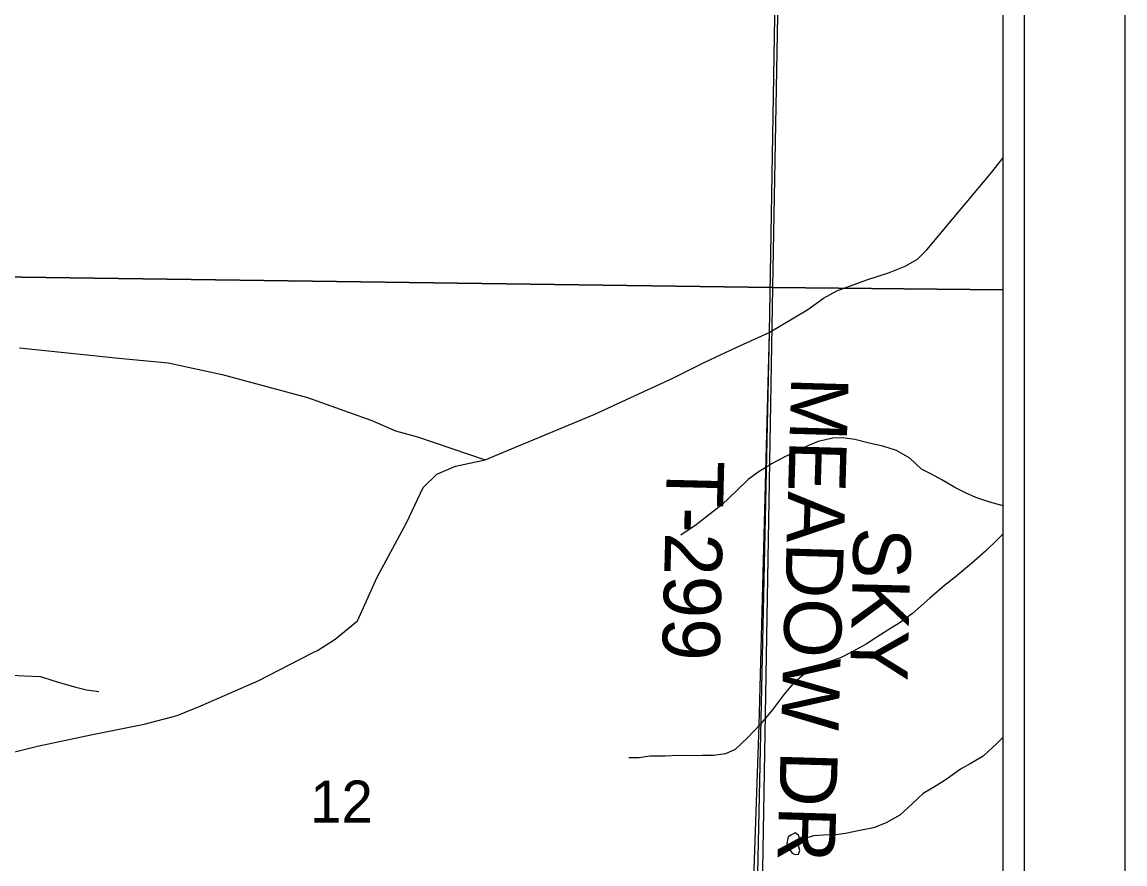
# Model space of a CAD drawing. Extents: x 0 to 34, y -2.3 to 22.
# Drawn here: x 7.907 to 9, y 18.764 to 19.599 of the extents above; entities that cross this region are included whole.
import ezdxf

# ---------------------------------------------------------------- set-up
doc = ezdxf.new("R2010")
doc.units = 0
for name, color, linetype in [('GM_X_County', 7, 'Continuous'), ('GM_X_Minor_River', 7, 'Continuous'), ('GM_X_Section', 7, 'Continuous'), ('GM_X_Section_Text', 7, 'Continuous'), ('GM_X_Township', 7, 'Continuous'), ('GM_X_Township_Road', 7, 'Continuous'), ('GM_X_Township_Road_Text', 7, 'Continuous'), ('SH_Data', 7, 'Continuous')]:
    doc.layers.add(name, color=color, linetype=linetype)

msp = doc.modelspace()

# ---------------------------------------------------------------- linework, layer by layer
at = {"layer": 'GM_X_County'}
msp.add_line((8.8792, 14.574), (8.8792, 20.8994), dxfattribs=at)
at = {"layer": 'GM_X_Minor_River'}
for p, q in [((8.6958, 19.1827), (8.6862, 19.1788)), ((8.7103, 19.1861), (8.6958, 19.1827)), ((8.7202, 19.1862), (8.7103, 19.1861)), ((8.7323, 19.1848), (8.7202, 19.1862)), ((8.7463, 19.181), (8.7323, 19.1848)), ((8.7599, 19.1779), (8.7463, 19.181)), ((8.6746, 19.173), (8.6627, 19.1676)), ((8.6862, 19.1788), (8.6746, 19.173)), ((8.7735, 19.1738), (8.7599, 19.1779)), ((8.7866, 19.1662), (8.7735, 19.1738)), ((8.6503, 19.1607), (8.6364, 19.1523)), ((8.6627, 19.1676), (8.6503, 19.1607)), ((8.7984, 19.1552), (8.7866, 19.1662)), ((8.6364, 19.1523), (8.6264, 19.145)), ((8.8082, 19.1504), (8.7984, 19.1552)), ((8.8183, 19.1448), (8.8082, 19.1504)), ((8.6264, 19.145), (8.6146, 19.1335)), ((8.8314, 19.1372), (8.8183, 19.1448)), ((8.8419, 19.1319), (8.8314, 19.1372)), ((8.6146, 19.1335), (8.6002, 19.1198)), ((8.852, 19.1271), (8.8419, 19.1319)), ((8.8659, 19.1225), (8.852, 19.1271)), ((8.6002, 19.1198), (8.5885, 19.1106)), ((8.8792, 19.119), (8.8659, 19.1225)), ((8.5885, 19.1106), (8.5749, 19.1)), ((8.5749, 19.1), (8.5598, 19.0897)), ((8.8737, 19.0854), (8.8616, 19.074)), ((8.8792, 19.0912), (8.8737, 19.0854)), ((8.8616, 19.074), (8.8479, 19.0618)), ((8.8479, 19.0618), (8.8316, 19.0481)), ((8.8316, 19.0481), (8.8211, 19.0397)), ((8.8211, 19.0397), (8.8067, 19.0271)), ((8.8067, 19.0271), (8.7895, 19.012)), ((8.7895, 19.012), (8.776, 19.0024)), ((8.7648, 18.9955), (8.7539, 18.9886)), ((8.776, 19.0024), (8.7648, 18.9955)), ((8.7539, 18.9886), (8.7435, 18.9816)), ((8.7288, 18.9736), (8.718, 18.9682)), ((8.7435, 18.9816), (8.7288, 18.9736)), ((8.7073, 18.9643), (8.6973, 18.96)), ((8.718, 18.9682), (8.7073, 18.9643)), ((7.8962, 18.9508), (7.9091, 18.9501)), ((7.9091, 18.9501), (7.9247, 18.9497)), ((7.9247, 18.9497), (7.9371, 18.9456)), ((8.6838, 18.9536), (8.6709, 18.9425)), ((8.6973, 18.96), (8.6838, 18.9536)), ((7.9371, 18.9456), (7.9469, 18.9426)), ((7.9469, 18.9426), (7.9597, 18.9389)), ((7.9597, 18.9389), (7.9703, 18.9363)), ((8.6709, 18.9425), (8.6623, 18.9321)), ((7.9703, 18.9363), (7.9828, 18.9348)), ((8.6623, 18.9321), (8.6504, 18.916)), ((8.6504, 18.916), (8.6383, 18.9019)), ((8.6383, 18.9019), (8.6261, 18.8889)), ((8.6261, 18.8889), (8.6136, 18.8771)), ((8.8792, 18.8893), (8.873, 18.883)), ((8.6136, 18.8771), (8.604, 18.8727)), ((8.873, 18.883), (8.8594, 18.8704)), ((8.5184, 18.869), (8.5081, 18.8689)), ((8.5291, 18.8706), (8.5184, 18.869)), ((8.5443, 18.8706), (8.5291, 18.8706)), ((8.5572, 18.8713), (8.5443, 18.8706)), ((8.5709, 18.871), (8.5572, 18.8713)), ((8.5808, 18.8711), (8.5709, 18.871)), ((8.5922, 18.8712), (8.5808, 18.8711)), ((8.604, 18.8727), (8.5922, 18.8712)), ((8.8466, 18.8628), (8.837, 18.8577)), ((8.8594, 18.8704), (8.8466, 18.8628)), ((8.837, 18.8577), (8.8226, 18.8474)), ((8.813, 18.8412), (8.7998, 18.8336)), ((8.8226, 18.8474), (8.813, 18.8412)), ((8.7998, 18.8336), (8.7889, 18.8232)), ((8.7889, 18.8232), (8.7768, 18.8121)), ((8.7768, 18.8121), (8.7633, 18.8045)), ((8.7372, 18.7968), (8.7231, 18.7938)), ((8.7506, 18.7995), (8.7372, 18.7968)), ((8.7633, 18.8045), (8.7506, 18.7995)), ((8.666, 18.7904), (8.6647, 18.784)), ((8.6695, 18.7926), (8.666, 18.7904)), ((8.6729, 18.7944), (8.6695, 18.7926)), ((8.6763, 18.792), (8.6729, 18.7944)), ((8.6774, 18.7893), (8.6763, 18.792)), ((8.6767, 18.7806), (8.6769, 18.7871)), ((8.6911, 18.7916), (8.6769, 18.7871)), ((8.6769, 18.7871), (8.6774, 18.7893)), ((8.701, 18.7921), (8.6911, 18.7916)), ((8.7136, 18.7925), (8.701, 18.7921)), ((8.7231, 18.7938), (8.7136, 18.7925)), ((8.6647, 18.784), (8.6672, 18.7786)), ((8.6672, 18.7786), (8.6701, 18.7743)), ((8.6765, 18.7734), (8.6778, 18.7771)), ((8.6778, 18.7771), (8.6767, 18.7806)), ((8.6701, 18.7743), (8.6731, 18.7731)), ((8.6731, 18.7731), (8.6765, 18.7734))]:
    msp.add_line(p, q, dxfattribs=at)
at = {"layer": 'GM_X_Section'}
for p, q in [((8.6694, 20.3414), (8.6506, 19.3353)), ((8.6694, 20.3414), (8.6506, 19.3353)), ((8.8792, 19.3331), (8.8792, 20.3383)), ((8.6506, 19.3353), (7.6398, 19.3493)), ((7.6398, 19.3493), (8.6506, 19.3353)), ((8.6506, 19.3353), (8.6333, 18.3353)), ((8.6506, 19.3353), (8.6333, 18.3353)), ((8.6506, 19.3353), (8.8792, 19.3331)), ((8.8792, 19.3331), (8.6506, 19.3353)), ((8.8792, 18.3339), (8.8792, 19.3331))]:
    msp.add_line(p, q, dxfattribs=at)
at = {"layer": 'GM_X_Township'}
for p, q in [((8.8792, 17.9482), (8.8792, 20.8994)), ((8.6549, 19.7576), (8.6474, 19.2909)), ((8.6549, 19.7576), (8.6474, 19.2909)), ((8.6474, 19.2909), (8.6171, 17.8851)), ((8.6474, 19.2909), (8.6171, 17.8851))]:
    msp.add_line(p, q, dxfattribs=at)
at = {"layer": 'GM_X_Township_Road'}
for p, q in [((8.8663, 19.448), (8.8792, 19.464)), ((8.8035, 19.3728), (8.8663, 19.448)), ((8.7942, 19.3635), (8.8035, 19.3728)), ((8.7656, 19.3499), (8.7821, 19.3565)), ((8.7821, 19.3565), (8.7942, 19.3635)), ((8.7442, 19.3432), (8.7656, 19.3499)), ((8.7145, 19.332), (8.7442, 19.3432)), ((8.6856, 19.3136), (8.701, 19.3249)), ((8.701, 19.3249), (8.7145, 19.332)), ((8.6474, 19.2909), (8.6856, 19.3136)), ((8.6147, 19.276), (8.6474, 19.2909)), ((8.6474, 19.2909), (8.637, 18.9012)), ((7.904, 19.2755), (8.0026, 19.2655)), ((8.5835, 19.2613), (8.6147, 19.276)), ((8.0026, 19.2655), (8.0514, 19.2608)), ((8.0514, 19.2608), (8.1049, 19.249)), ((8.5518, 19.2454), (8.5835, 19.2613)), ((8.1049, 19.249), (8.1896, 19.2264)), ((8.51, 19.2264), (8.5518, 19.2454)), ((8.1896, 19.2264), (8.2534, 19.2034)), ((8.4745, 19.2099), (8.51, 19.2264)), ((8.2534, 19.2034), (8.2768, 19.1931)), ((8.384, 19.1722), (8.4745, 19.2099)), ((8.2768, 19.1931), (8.2985, 19.1873)), ((8.2985, 19.1873), (8.3656, 19.1645)), ((8.3656, 19.1645), (8.384, 19.1722)), ((8.3179, 19.1503), (8.3364, 19.1583)), ((8.3364, 19.1583), (8.3656, 19.1645)), ((8.3043, 19.1372), (8.3179, 19.1503)), ((8.2876, 19.102), (8.3043, 19.1372)), ((8.2587, 19.0482), (8.2876, 19.102)), ((8.2391, 19.0049), (8.2587, 19.0482)), ((8.217, 18.9867), (8.2391, 19.0049)), ((8.1995, 18.9754), (8.217, 18.9867)), ((8.1817, 18.9664), (8.1966, 18.9739)), ((8.1966, 18.9739), (8.1995, 18.9754)), ((8.1413, 18.9455), (8.1817, 18.9664)), ((8.0839, 18.9203), (8.1413, 18.9455)), ((8.0604, 18.9108), (8.0839, 18.9203)), ((8.0276, 18.9022), (8.0604, 18.9108)), ((7.9763, 18.8921), (8.0276, 18.9022)), ((8.637, 18.9012), (8.631, 18.7227)), ((7.922, 18.8804), (7.9763, 18.8921)), ((7.8742, 18.8687), (7.922, 18.8804))]:
    msp.add_line(p, q, dxfattribs=at)
at = {"layer": 'SH_Data'}
for p, q in [((9, 21), (9, 14)), ((8.9, 20.9), (8.9, 14.1))]:
    msp.add_line(p, q, dxfattribs=at)

# ---------------------------------------------------------------- texts
at = {"layer": 'GM_X_Section_Text'}
msp.add_text('12', height=0.04186, rotation=0, dxfattribs=at).set_placement((8.1921, 18.8045))
at = {"layer": 'GM_X_Township_Road_Text'}
for s, rotation, p in [('MEADOW DR', 268.3507, (8.6693, 19.2474)), ('T-299', 268.5962, (8.546, 19.1644)), ('SKY', 268.628, (8.7312, 19.098))]:
    msp.add_text(s, height=0.05682, rotation=rotation, dxfattribs=at).set_placement(p)

doc.saveas('drawing.dxf')
